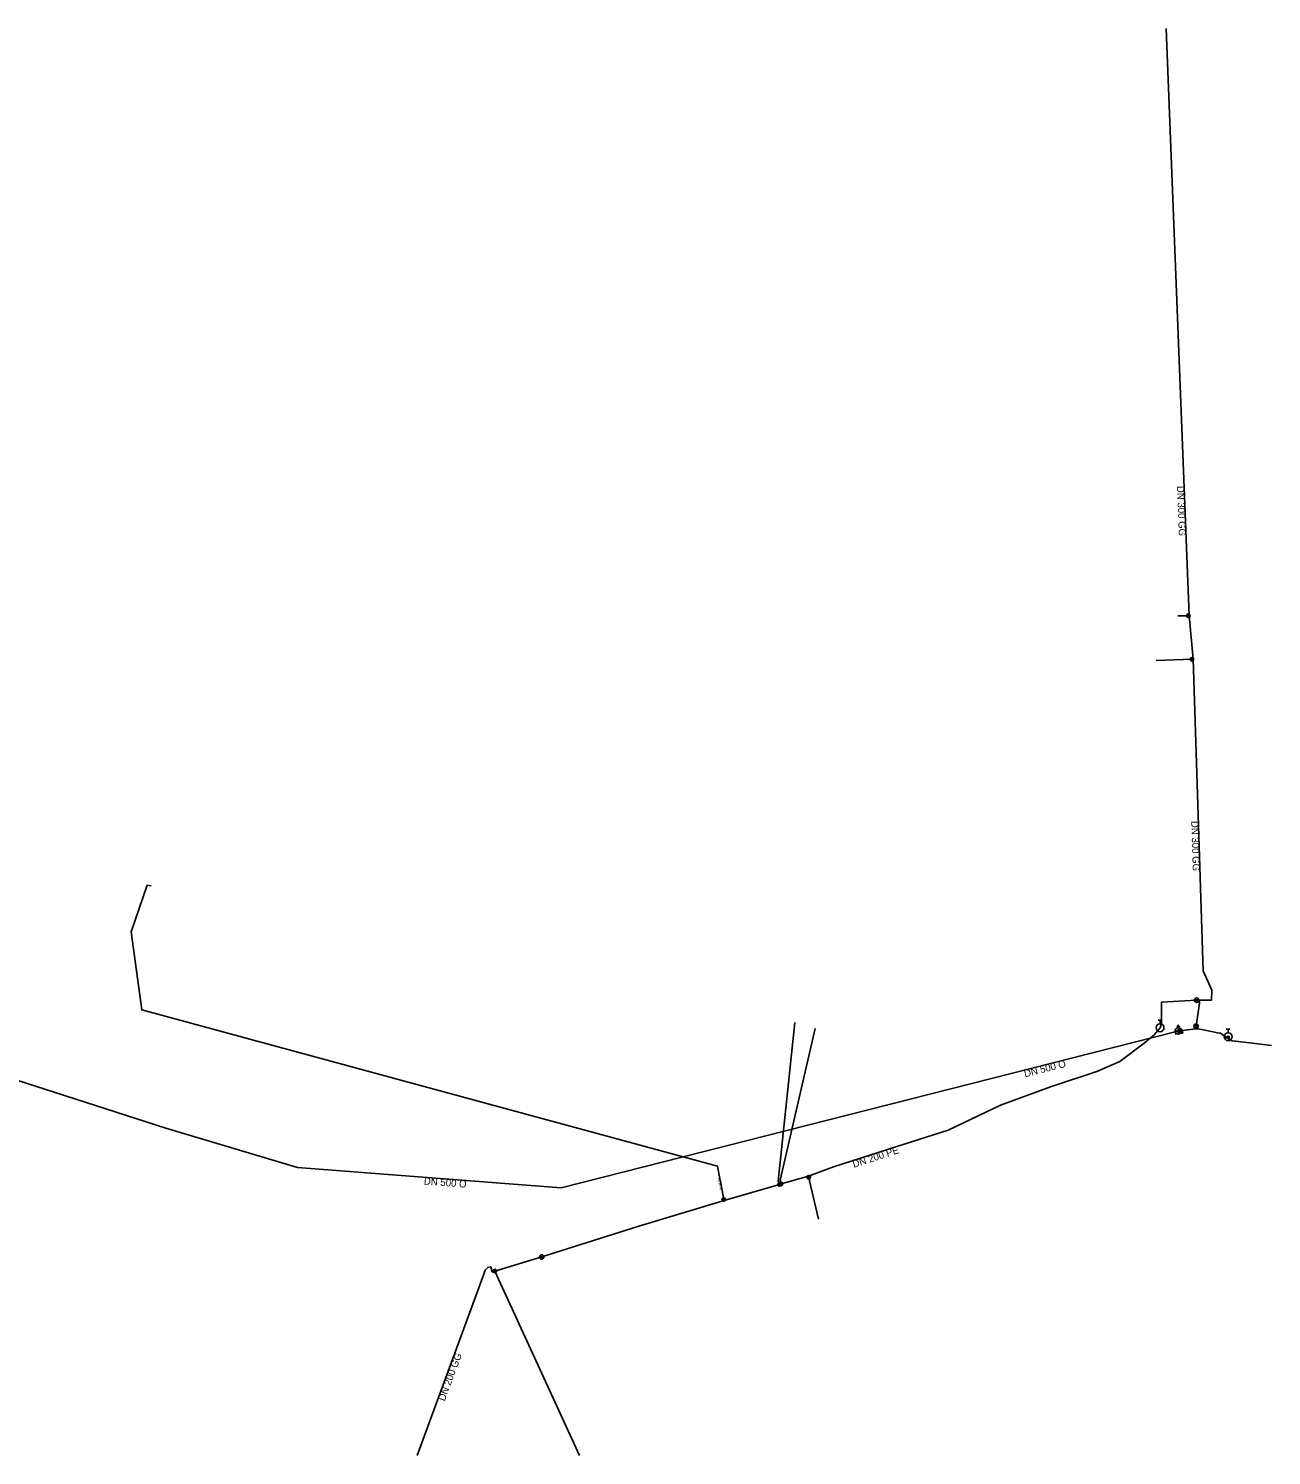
# Model space of a CAD drawing. Extents: x -464617 to -463917, y -1094288 to -1093929.
# Drawn here: x -464194.4 to -463916.9, y -1094287.7 to -1093969.2 of the extents above; entities that cross this region are included whole.
import ezdxf

# ---------------------------------------------------------------- set-up
doc = ezdxf.new("R2010")
doc.units = 0
for name, color, linetype in [('_hydrantova_odbocka_', 7, 'Continuous'), ('_pripojka_prevzato_z_dokumentace_', 7, 'Continuous'), ('_pripojka_priblizne_', 7, 'Continuous'), ('_voda_smvak_prevzato_z_dokumentace_', 7, 'Continuous'), ('_voda_smvak_priblizne_', 7, 'Continuous'), ('_vodovodni_chranicka_', 7, 'Continuous'), ('Default', 7, 'Continuous'), ('MoLevel 27', 7, 'Continuous'), ('MoLevel 28', 7, 'Continuous'), ('MoLevel 30', 7, 'Continuous'), ('MoLevel 42', 7, 'Continuous'), ('MoLevel 46', 7, 'Continuous'), ('MoLevel 53', 7, 'Continuous'), ('MoLevel 55', 7, 'Continuous')]:
    doc.layers.add(name, color=color, linetype=linetype)

# ---------------------------------------------------------------- blocks, each defined once
blk = doc.blocks.new('_uzaver_')
at = {"layer": 'Default'}
for p, q in [((-0.000035, -0.000035), (0.000035, 0.000035)), ((0.000035, -0.000035), (-0.000035, 0.000035))]:
    blk.add_line(p, q, dxfattribs=at)
for radius in [0.00005, 0.0000025]:
    blk.add_circle((0, 0), radius, dxfattribs=at)
blk = doc.blocks.new('_uzaver_pripojka_')
at = {"layer": 'Default'}
for p, q in [((-0.000035, -0.000035), (0.000035, 0.000035)), ((0.000035, -0.000035), (-0.000035, 0.000035))]:
    blk.add_line(p, q, dxfattribs=at)
for radius in [0.00005, 0.0000025]:
    blk.add_circle((0, 0), radius, dxfattribs=at)
blk = doc.blocks.new('_hydrant_voda_')
at = {"layer": 'Default'}
for p, q in [((-0.000023, 0.000095), (0.000023, 0.000095)), ((0, 0.000095), (0, 0.00005))]:
    blk.add_line(p, q, dxfattribs=at)
blk.add_circle((0, 0), 0.00005, dxfattribs=at)
blk = doc.blocks.new('_sachta_voda_')
at = {"layer": 'Default'}
blk.add_line((0, 0.000035), (0, 0.00005), dxfattribs=at)
blk.add_lwpolyline([(-0.000015, 0.00005), (0, 0.000065), (0.000015, 0.00005), (0.000003, 0.00005)], close=True, dxfattribs=at)
blk.add_circle((0, 0), 0.000035, dxfattribs=at)
blk = doc.blocks.new('_poklop_voda_')
at = {"layer": 'Default'}
blk.add_lwpolyline([(-0.00002, 0.00002), (0.00002, 0.00002), (0.00002, -0.00002), (-0.00002, -0.00002), (-0.00002, 0.00002)], dxfattribs=at)

msp = doc.modelspace()

# ---------------------------------------------------------------- linework, layer by layer
at = {"layer": '_hydrantova_odbocka_'}
msp.add_line((-463926.51, -1094194.71), (-463926.55, -1094194.24), dxfattribs=at)
at = {"layer": '_pripojka_prevzato_z_dokumentace_'}
for p, q in [((-464026.73, -1094227.22), (-464027.01, -1094226.48)), ((-464026.58, -1094226.26), (-464026.36, -1094227.11))]:
    msp.add_line(p, q, dxfattribs=at)
for points in [[(-464039.12, -1094230.8), (-464039.2, -1094230.58), (-464040, -1094226.2)], [(-464020.23, -1094225.4), (-464020.21, -1094225.61), (-464020.05, -1094226.42)]]:
    msp.add_lwpolyline(points, dxfattribs=at)
at = {"layer": '_pripojka_priblizne_'}
for p, q in [((-464023.31, -1094191.1), (-464027.01, -1094226.49)), ((-464018.79, -1094192.37), (-464026.58, -1094226.27)), ((-464018.04, -1094234.98), (-464020.05, -1094226.42)), ((-464071.4, -1094287.71), (-464090.31, -1094246.54))]:
    msp.add_line(p, q, dxfattribs=at)
for points in [[(-463937.77, -1094100.29), (-463935.46, -1094100.26), (-463935.24, -1094100.22)], [(-463942.61, -1094110.24), (-463934.61, -1094109.98), (-463934.33, -1094109.99)], [(-464167.09, -1094160.54), (-464167.93, -1094160.41), (-464171.53, -1094170.84), (-464169.16, -1094188.24), (-464040.56, -1094223.15), (-464039.98, -1094226.3)]]:
    msp.add_lwpolyline(points, dxfattribs=at)
at = {"layer": '_voda_smvak_prevzato_z_dokumentace_'}
for p, q in [((-463933.59, -1094186.07), (-463932.97, -1094186.08)), ((-463933.75, -1094192.47), (-463936.76, -1094192.84)), ((-463933.75, -1094192.47), (-463933.71, -1094191.9)), ((-463936.76, -1094192.84), (-463937.31, -1094192.9)), ((-464092.73, -1094247.25), (-464107.65, -1094287.71))]:
    msp.add_line(p, q, dxfattribs=at)
for points in [[(-463940.41, -1093969.19), (-463935.24, -1094100.22), (-463934.33, -1094109.99), (-463932.11, -1094179.56), (-463930.2, -1094183.86)], [(-463938.35, -1094193.12), (-464075.49, -1094227.95), (-464134.41, -1094223.46), (-464163.79, -1094214.62), (-464202, -1094202.35), (-464255.09, -1094244.35), (-464271.29, -1094237.84), (-464272.2, -1094237.58), (-464367.49, -1094207.05), (-464368.8, -1094203.51), (-464371.89, -1094195.64), (-464375, -1094191.05), (-464437.3, -1094167.91), (-464498.99, -1094146.23), (-464538.72, -1094132.85), (-464555.61, -1094126.9), (-464559.83, -1094125.15), (-464564.5, -1094123.44), (-464565.5, -1094123.21)], [(-463941.76, -1094192.23), (-463941.45, -1094191.25), (-463941.41, -1094186.52), (-463933.59, -1094186.07)], [(-463932.97, -1094186.08), (-463932.97, -1094186.76), (-463933.71, -1094191.9)], [(-463930.2, -1094183.86), (-463930.26, -1094186.07), (-463930.3, -1094186.08), (-463932.97, -1094186.08)], [(-464079.85, -1094243.4), (-464058.17, -1094236.51), (-464039.12, -1094230.8), (-464026.73, -1094227.22), (-464026.36, -1094227.11), (-464020.23, -1094225.4), (-464014.67, -1094223.3), (-464000.54, -1094218.71), (-463989.04, -1094215.07), (-463977.36, -1094209.48), (-463965.98, -1094205.32), (-463955.86, -1094201.99), (-463950.75, -1094199.79), (-463945.29, -1094195.68), (-463943.09, -1094193.83), (-463941.76, -1094192.23)], [(-463933.75, -1094192.47), (-463933.26, -1094192.48), (-463932.05, -1094192.73), (-463928.56, -1094193.41), (-463928.29, -1094193.48), (-463928.07, -1094193.56), (-463926.51, -1094194.71)], [(-463937.31, -1094192.9), (-463937.71, -1094192.95), (-463938.35, -1094193.12)], [(-463926.51, -1094194.71), (-463926.04, -1094194.97), (-463925.86, -1094195.07), (-463925.7, -1094195.13), (-463922.96, -1094195.48), (-463916.87, -1094196.17)], [(-464092.73, -1094247.25), (-464092.46, -1094246.35), (-464091.85, -1094245.78), (-464091.22, -1094245.62), (-464090.88, -1094246.74), (-464090.31, -1094246.54), (-464079.85, -1094243.4)]]:
    msp.add_lwpolyline(points, dxfattribs=at)
at = {"layer": '_voda_smvak_priblizne_'}
for p, q in [((-463938.35, -1094193.12), (-463938.29, -1094193.36)), ((-463936.72, -1094193.13), (-463936.76, -1094192.84))]:
    msp.add_line(p, q, dxfattribs=at)
for points in [[(-463938.29, -1094193.36), (-463938.22, -1094193.67), (-463937.44, -1094193.55)], [(-463937.44, -1094193.55), (-463936.68, -1094193.44), (-463936.72, -1094193.13)]]:
    msp.add_lwpolyline(points, dxfattribs=at)
at = {"layer": '_vodovodni_chranicka_'}
msp.add_lwpolyline([(-463925.5, -1094195.16), (-463922.96, -1094195.48), (-463916.87, -1094196.17)], dxfattribs=at)

# ---------------------------------------------------------------- block references
at = {"layer": 'MoLevel 27', "xscale": 10000, "yscale": 10000}
for p in [(-463933.59, -1094186.07), (-464079.85, -1094243.4)]:
    msp.add_blockref('_uzaver_', p, dxfattribs=at)
at = {"layer": 'MoLevel 27'}
for p, xscale, yscale, rotation in [((-463937.31, -1094192.9), 10000, 10000.000000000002, -166.53747482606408), ((-463933.71, -1094191.9), 9999.999999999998, 10000, 85.6776590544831), ((-463926.53, -1094194.39), 5000, 5000, 93.3664606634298)]:
    msp.add_blockref('_uzaver_', p, dxfattribs=dict(at, xscale=xscale, yscale=yscale, rotation=rotation))
at = {"layer": 'MoLevel 28', "xscale": 17636.68430335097, "yscale": 17636.68430335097}
for p in [(-463941.76, -1094192.23), (-463926.55, -1094194.24)]:
    msp.add_blockref('_hydrant_voda_', p, dxfattribs=at)
at = {"layer": 'MoLevel 30', "xscale": 20000, "yscale": 20000}
msp.add_blockref('_sachta_voda_', (-463937.71, -1094192.95), dxfattribs=at)
at = {"layer": 'MoLevel 42', "xscale": 10000, "yscale": 10000}
msp.add_blockref('_poklop_voda_', (-463937.71, -1094192.95), dxfattribs=at)
at = {"layer": 'MoLevel 53', "xscale": 7999.999999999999, "yscale": 7999.999999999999}
for p in [(-463935.46, -1094100.26), (-463934.61, -1094109.98), (-464026.73, -1094227.22), (-464026.36, -1094227.11), (-464020.21, -1094225.61), (-464039.2, -1094230.58)]:
    msp.add_blockref('_uzaver_pripojka_', p, dxfattribs=at)
at = {"layer": 'MoLevel 53', "xscale": 8000, "yscale": 7999.999999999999, "rotation": 16.7092943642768}
msp.add_blockref('_uzaver_pripojka_', (-464090.31, -1094246.54), dxfattribs=at)

# ---------------------------------------------------------------- texts
at = {"layer": 'MoLevel 46'}
for s, rotation, p in [('DN 300 GG', 272.2587, (-463937.99, -1094071.31)), ('DN 300 GG', 271.8284, (-463934.79, -1094146.09)), ('DN 500 O', 14.2534, (-463971.91, -1094203.3)), ('DN 200 PE', 17.9959, (-464010.13, -1094223.51)), ('DN 500 O', 355.643, (-464106.2, -1094227.22)), ('DN 200 GG', 69.7553, (-464101.51, -1094275.7))]:
    msp.add_text(s, height=1.605, rotation=rotation, dxfattribs=at).set_placement(p)
at = {"layer": 'MoLevel 55'}
msp.add_text('DN 80 PE', height=0.455, rotation=280.3509, dxfattribs=at).set_placement((-464040.53, -1094225.82))

doc.saveas('drawing.dxf')
